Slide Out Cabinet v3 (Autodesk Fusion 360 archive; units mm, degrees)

design "Slide Out Cabinet" references "18  Drawer Slide"
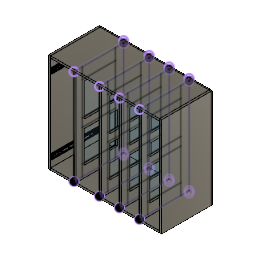
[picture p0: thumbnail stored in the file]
sketch "Sketch1" plane through (0, 0, 0) normal (0, 1, 0) x axis (1, 0, 0)
  line L1 (1041.4, 0) -> (0, 0)
  line L2 (1041.4, -914.4) -> (1041.4, 0)
  line L3 (0, -914.4) -> (1041.4, -914.4)
  line L4 (0, 0) -> (0, -914.4)
  point P1 (0, 0)
  point P2 (0, 0)
  point P3 (1041.4, 0)
  point P5 (0, -914.4)
  horizontal L1
  vertical L2
  horizontal L3
  vertical L4
  coincident P1 P2
  dimension "d1" distance P2 P3 = 1041.4
  dimension "d2" distance P2 P5 = 914.4
extrude "Extrude1" new body sketch "Sketch1" along normal blind 12.7 (= "1/2")
sketch "Sketch1" plane through (0, 0, 0) normal (0, -1, 0) x axis (1, 0, 0)
  line L1 (0, 914.4) -> (1041.4, 914.4)
  line L2 (0, 0) -> (0, 914.4)
  line L3 (1041.4, 0) -> (0, 0)
  line L4 (1041.4, 914.4) -> (1041.4, 0)
  line L5 (19.05, 0) -> (0, 0)
  line L6 (19.05, 914.4) -> (19.05, 0)
  line L7 (0, 914.4) -> (19.05, 914.4)
  line L8 (0, 0) -> (0, 914.4)
  point P4 (0, 0)
  point P6 (0, 0)
  point P7 (19.05, 0)
  point P9 (0, 914.4)
  horizontal L5
  vertical L6
  horizontal L7
  vertical L8
  coincident P4 P6
  dimension "d5" distance P6 P7 = 19.05 (= "3/4")
  dimension "d6" distance P6 P9 = 914.4 (= "36")
extrude "Extrude1" new body sketch "Sketch1" profile of L1 L2 L3 L5 L6 L7 L8 along normal blind 457.2
work_plane "WorkPlane1"
work_plane "WorkPlane2"
mirror_component "MirrorComponent1"
derived_instance "DerivedInstance1"
as_built_joint "As-built1"
as_built_joint "As-built2"
ground "Ground1"
ground "Ground2"
ground "Ground3"
sketch "Sketch1" plane through (0, 0, 914.4) normal (0, 0, 1) x axis (-1, 0, 0)
  line L1 (-1041.4, 0) -> (0, 0)
  line L2 (-1041.4, -12.7) -> (-1041.4, 0)
  line L3 (0, -12.7) -> (-1041.4, -12.7)
  line L4 (0, 0) -> (0, -12.7)
  line L5 (-1022.35, 0) -> (-19.05, 0)
  line L6 (-1022.35, 457.2) -> (-1022.35, 0)
  line L7 (-19.05, 457.2) -> (-1022.35, 457.2)
  line L8 (-19.05, 0) -> (-19.05, 457.2)
  point P8 (-1022.35, 457.2)
  point P11 (-1022.35, 457.2)
  point P6 (-19.05, 0)
  point P10 (-19.05, 0)
  horizontal L5
  vertical L6
  horizontal L7
  vertical L8
  coincident P8 P11
  coincident P6 P10
extrude "Extrude1" new body sketch "Sketch1" profile of L1 L5 L6 L7 L8 against normal blind 19.05 (magnitude of "-3/4")
mirror_component "MirrorComponent2"
derived_instance "DerivedInstance2"
as_built_joint "As-built3"
as_built_joint "As-built4"
sketch "Sketch1" plane through (19.05, 0, 0) normal (1, 0, 0) x axis (0, 1, 0)
  line L1 (0, 914.4) -> (0, 0)
  line L2 (-457.2, 914.4) -> (0, 914.4)
  line L3 (-457.2, 0) -> (-457.2, 914.4)
  line L4 (0, 0) -> (-457.2, 0)
  line L5 (0, 19.05) -> (-457.2, 19.05)
  line L6 (0, 895.35) -> (0, 19.05)
  line L7 (-457.2, 895.35) -> (0, 895.35)
  line L8 (-457.2, 19.05) -> (-457.2, 895.35)
  line L9 (-381, 19.05) -> (-381, 895.35)
  line L10 (-76.2, 895.35) -> (-76.2, 19.05)
  line L11 (-76.2, 793.75) -> (-381, 793.75)
  line L12 (-76.2, 488.95) -> (-381, 488.95)
  line L13 (-76.2, 412.75) -> (-381, 412.75)
  line L14 (-76.2, 120.65) -> (-381, 120.65)
  line L15 (0, 914.4) -> (0, 0)
  line L16 (-457.2, 895.35) -> (0, 895.35)
  line L17 (-457.2, 19.05) -> (0, 19.05)
  point P8 (0, 895.35)
  point P11 (0, 895.35)
  point P6 (-457.2, 19.05)
  point P10 (-457.2, 19.05)
  point P12 (-381, 895.35)
  point P13 (-381, 19.05)
  point P14 (-76.2, 19.05)
  point P15 (-76.2, 895.35)
  point P16 (-381, 793.75)
  point P17 (-76.2, 793.75)
  point P18 (-381, 488.95)
  point P19 (-76.2, 488.95)
  point P20 (-381, 412.75)
  point P21 (-76.2, 412.75)
  point P22 (-381, 120.65)
  point P23 (-76.2, 120.65)
  horizontal L5
  vertical L6
  horizontal L7
  vertical L8
  coincident P8 P11
  coincident P6 P10
  coincident L7 P12
  coincident L5 P13
  perpendicular L5 L9
  coincident L5 P14
  coincident L7 P15
  perpendicular L7 L10
  coincident L9 P16
  coincident L10 P17
  perpendicular L10 L11
  coincident L9 P18
  coincident L10 P19
  perpendicular L10 L12
  coincident L9 P20
  coincident L10 P21
  perpendicular L10 L13
  coincident L9 P22
  coincident L10 P23
  perpendicular L10 L14
  dimension "d13" distance L8 L9 = 76.2
  dimension "d14" distance L10 L15 = 76.2
  dimension "d15" distance L11 L16 = 101.6
  dimension "d16" distance L12 L13 = 76.2
  dimension "d17" distance L14 L17 = 101.6
  dimension "d18" distance L13 L14 = 292.1
extrude "Extrude2" new body sketch "Sketch1" profile of L1 L3 L5 L6 L7 L8 L9 L10 L11 L12 L13 L14 L15 L16 L17 along normal blind 19.05 (= "3/4")
position "Position1"
as_built_joint "As-built5"
copy_paste "CopyPaste1"
copy_paste "CopyPaste2"
copy_paste "CopyPaste3"
as_built_joint "As-built4"
as_built_joint "As-built5"
as_built_joint "As-built6"
position "Position2"
combine "Combine1"
remove_instance "RemoveInstance1"
combine "Combine1"
remove_instance "RemoveInstance2"
position "Position3"
component_insert "Component Insert1"
joint "Assemble1" alignAngle 0 alignOffsetX 0 (= "0") alignOffsetY -88.9 (= "-3 1/2") alignOffsetZ 0 (= "0")
component_insert "Component Insert2"
joint "Assemble2" alignAngle -90 alignOffsetX 0 (= "0") alignOffsetY 96.4406 (= "3 51/64") alignOffsetZ 0 (= "0")
copy_paste "CutPaste1"
copy_paste "CutPaste2"
copy_paste "CutPaste3"
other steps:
derived_base_feature "Derived Base Feature1"
derived_base_feature "Derived Base Feature1"
create_component "CreateComponent1"
create_component "CreateComponent1"
create_component "CreateComponent1"
create_component "CreateComponent2"
create_component "CreateComponent3"
create_component "CreateComponent4"
create_component "CreateComponent5"
create_component "CreateComponent6"
create_component "CreateComponent2"
create_component "CreateComponent3"
joint_origin "JointOrigin1"
joint_origin "JointOrigin2"
remove_instance "RemoveInstance1"
remove_instance "RemoveInstance2"
remove_instance "RemoveInstance3"

design "18  Drawer Slide"
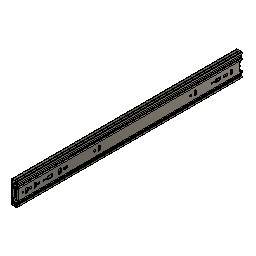
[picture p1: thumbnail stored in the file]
base_feature "Base Feature1"
combine "Combine1"
combine "Combine1"
remove_body "RemoveBody6"
remove_body "RemoveBody7"
component_from_bodies "Body->Comp"
position "Position3"
ground "Ground4"
as_built_joint "As-built2" OffsetX 0 (= "0") named "d28_1" OffsetY 0 (= "0") named "d29_1" OffsetZ 0 (= "0") named "d30_1" AngleZ 0 named "d31_1" SlideMinimum -228.6 named "d32_1" SlideMaximum 0 (= "0") named "d33_1" SlideRest -228.6 named "d34_1"
as_built_joint "As-built3" OffsetX 0 (= "0") named "d35_1" OffsetY 0 (= "0") named "d36_1" OffsetZ 0 (= "0") named "d37_1" AngleZ 0 named "d38_1" SlideMinimum -228.6 named "d39_1" SlideMaximum 0 (= "0") named "d40_1" SlideRest -228.6 named "d41_1"
ground "Ground5"
position "Position1"
ground "Ground1"
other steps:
base_feature "Base Feature1"
remove_body "RemoveBody1"
remove_body "RemoveBody2"
remove_body "RemoveBody3"
remove_body "RemoveBody4"
remove_body "RemoveBody5"
create_component "CreateComponent1"
remove_body "RemoveBody8"
create_component "CreateComponent1"
create_component "CreateComponent2"
create_component "CreateComponent3"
